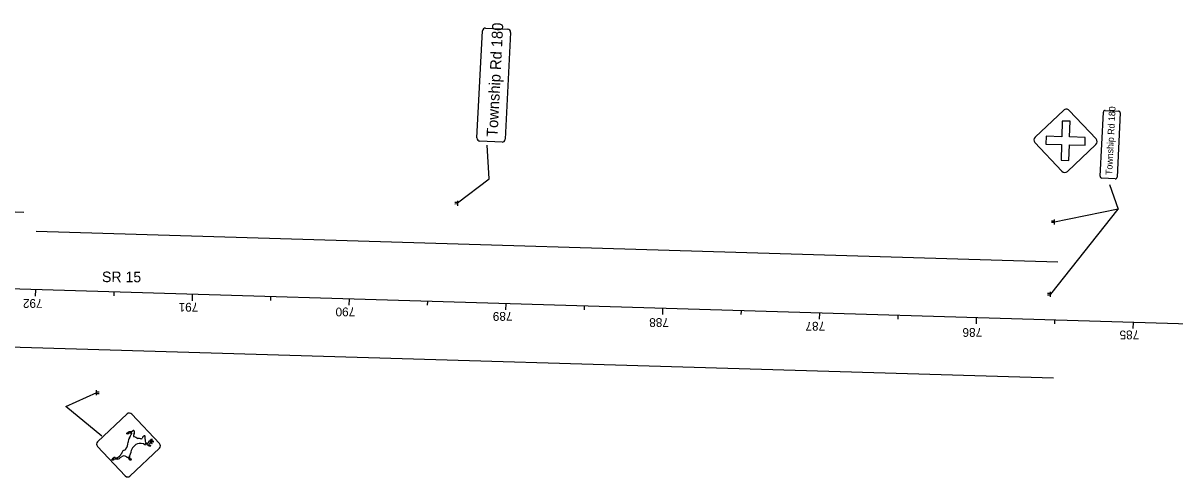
# Model space of a CAD drawing. Extents: x 1658454 to 1663955, y 480219 to 484109.
# Drawn here: x 1661744 to 1662479, y 482582 to 482871 of the extents above; entities that cross this region are included whole.
import ezdxf

# ---------------------------------------------------------------- set-up
doc = ezdxf.new("R2010")
doc.units = 0
for name, color, linetype in [('Default', 7, 'Continuous'), ('PM_P_Edge_Line', 7, 'Continuous'), ('PM_X_Lane_Line', 7, 'Continuous'), ('SC_Scratch1', 7, 'Continuous'), ('SN_X_Public', 7, 'Continuous'), ('SV_X_CL_Survey_50', 7, 'Continuous'), ('SV_X_Text', 7, 'Continuous')]:
    doc.layers.add(name, color=color, linetype=linetype)

msp = doc.modelspace()

# ---------------------------------------------------------------- linework, layer by layer
at = {"layer": 'Default'}
for p, q in [((1661752.21, 482700.93), (1661752.09, 482696.94)), ((1661802.19, 482699.45), (1661802.12, 482697.05)), ((1661852.17, 482697.97), (1661852.05, 482693.97)), ((1661902.15, 482696.48), (1661902.07, 482694.08)), ((1661952.12, 482695), (1661952.01, 482691)), ((1662002.1, 482693.51), (1662002.03, 482691.12)), ((1662052.08, 482692.03), (1662051.96, 482688.03)), ((1662102.06, 482690.55), (1662101.99, 482688.15)), ((1662152.04, 482689.06), (1662151.92, 482685.06)), ((1662202.01, 482687.58), (1662201.94, 482685.18)), ((1662251.99, 482686.1), (1662251.87, 482682.1)), ((1662301.97, 482684.61), (1662301.9, 482682.21)), ((1662351.95, 482683.13), (1662351.83, 482679.13)), ((1662401.93, 482681.64), (1662401.85, 482679.24)), ((1662451.9, 482680.16), (1662451.79, 482676.16))]:
    msp.add_line(p, q, dxfattribs=at)
at = {"layer": 'PM_P_Edge_Line'}
msp.add_line((1661744.74, 482750.18), (1661423, 482759.73), dxfattribs=at)
at = {"layer": 'PM_X_Lane_Line'}
for p, q in [((1662403.89, 482718.6), (1661752.68, 482737.94)), ((1662401.15, 482644.65), (1661431.82, 482673.43))]:
    msp.add_line(p, q, dxfattribs=at)
at = {"layer": 'SC_Scratch1'}
for p, q in [((1662039.2, 482867.58), (1662053.34, 482866.86)), ((1662033.69, 482797.69), (1662037.18, 482865.76)), ((1662055.16, 482864.84), (1662051.67, 482796.77)), ((1662434.21, 482815.16), (1662442.7, 482814.73)), ((1662406.74, 482808.39), (1662406.44, 482798.39)), ((1662411.74, 482808.24), (1662406.74, 482808.39)), ((1662411.44, 482798.25), (1662411.74, 482808.24)), ((1662430.91, 482773.23), (1662433, 482814.07)), ((1662443.79, 482813.52), (1662441.69, 482772.67)), ((1662049.65, 482794.95), (1662035.51, 482795.67)), ((1662396.45, 482798.69), (1662396.3, 482793.69)), ((1662396.3, 482793.69), (1662406.29, 482793.4)), ((1662406.44, 482798.39), (1662396.45, 482798.69)), ((1662406.29, 482793.4), (1662406, 482783.4)), ((1662411, 482783.25), (1662411.29, 482793.25)), ((1662411.29, 482793.25), (1662421.29, 482792.95)), ((1662421.44, 482797.95), (1662411.44, 482798.25)), ((1662421.29, 482792.95), (1662421.44, 482797.95)), ((1662406, 482783.4), (1662411, 482783.25)), ((1662440.48, 482771.58), (1662432, 482772.02)), ((1662399.52, 482698.16), (1662442.34, 482752.22)), ((1661821.36, 482602.84), (1661819.61, 482602.98)), ((1661819.62, 482605.88), (1661820.32, 482606.09))]:
    msp.add_line(p, q, dxfattribs=at)
for points in [[(1662407.68, 482815.31), (1662389.48, 482798.17)], [(1662428.36, 482797.01), (1662411.21, 482815.21)], [(1662021.28, 482756.24), (1662041.51, 482771.51), (1662040.18, 482793.13)], [(1662389.38, 482794.63), (1662406.52, 482776.44)], [(1662410.06, 482776.33), (1662428.25, 482793.48)], [(1662436.92, 482768.07), (1662442.34, 482752.22), (1662400.85, 482743.79)], [(1661794.62, 482607.57), (1661771.6, 482626.55), (1661791.28, 482635.41)], [(1661791.89, 482604.09), (1661810.66, 482621.78)], [(1661813.63, 482621.69), (1661831.33, 482602.91)], [(1661811.2, 482608.94), (1661810.38, 482609.14), (1661810.57, 482609.52), (1661811.94, 482610.61), (1661813.36, 482610.57), (1661814.46, 482611.21)], [(1661813.46, 482609.69), (1661812.98, 482609.63), (1661812.3, 482609.61)], [(1661815.12, 482607.34), (1661816.27, 482606.95), (1661817.53, 482606.07)], [(1661822.23, 482601.86), (1661822.1, 482602.06), (1661821.28, 482602.57), (1661821.36, 482602.84), (1661821.36, 482602.84)], [(1661809.49, 482582.34), (1661791.8, 482601.12)], [(1661831.24, 482599.95), (1661812.46, 482582.25)], [(1661804.65, 482593.03), (1661802.16, 482593.11), (1661801.83, 482592.43), (1661800.89, 482592.46), (1661801.86, 482593.62)]]:
    msp.add_lwpolyline(points, dxfattribs=at)
for centre, radius, start, end in [((1662039.1, 482865.66), 1.92, 87.06499, 177.06499), ((1662053.24, 482864.94), 1.92, 357.06499, 87.06499), ((1662409.39, 482813.49), 2.5, 43.29934, 133.29934), ((1662434.15, 482814.01), 1.15, 87.06499, 177.06499), ((1662442.64, 482813.58), 1.15, 357.06499, 87.06499), ((1662035.61, 482797.59), 1.92, 177.06499, 267.06499), ((1662049.75, 482796.86), 1.92, 267.06499, 357.06499), ((1662391.2, 482796.35), 2.5, 133.29934, 223.29934), ((1662426.54, 482795.3), 2.5, 313.29934, 43.29934), ((1662408.34, 482778.15), 2.5, 223.29934, 313.29934), ((1662432.06, 482773.17), 1.15, 177.06499, 267.06499), ((1662440.54, 482772.73), 1.15, 267.06499, 357.06499), ((1661812.1, 482620.25), 2.1, 43.29934, 133.29934), ((1661812.32, 482608.34), 1.28, 91.2294, 151.83119), ((1661813.55, 482609.65), 0.0933, 20.88729, 155.71139), ((1661813.25, 482609.53), 0.413, 335.71139, 20.88729), ((1661814.75, 482610.7), 0.593, 2.63463, 120.19731), ((1661811.58, 482610.55), 3.77, 340.37674, 2.63463), ((1661793.33, 482602.56), 2.1, 133.29934, 223.29934), ((1661802.43, 482604.17), 8.84, 328.01516, 357.51473), ((1661816.93, 482603.54), 5.68, 147.98842, 177.51473), ((1661792.03, 482619.11), 23.69, 327.98842, 335.71139), ((1661816.27, 482607.75), 1.5, 169.5087, 187.08998), ((1661815.04, 482607.6), 0.265, 187.08998, 286.39166), ((1661822.85, 482606.53), 8.2, 160.37674, 169.5087), ((1661819.14, 482597.1), 5.9, 85.48239, 130.64019), ((1661818.19, 482601.65), 4.47, 71.32687, 98.40328), ((1661822.18, 482606.1), 1.86, 123.54589, 180.45104), ((1661821.32, 482607.4), 0.304, 68.59738, 123.54589), ((1661823.43, 482606.08), 2.56, 133.2682, 141.14025), ((1661821.81, 482607.79), 0.208, 29.98489, 133.2682), ((1661825.01, 482606.96), 3.16, 162.61939, 208.96231), ((1661822.23, 482602.81), 0.0793, 70.11299, 252.53377), ((1661821.43, 482602.28), 0.902, 332.40863, 30.2681), ((1661828.3, 482604.88), 6.08, 174.86266, 191.04392), ((1661820.89, 482599.1), 4.02, 52.27544, 70.11299), ((1661823.35, 482604.45), 1.26, 215.889, 320.70968), ((1661826, 482605.7), 4.32, 232.27544, 253.45969), ((1661782.51, 482637.87), 54.02, 320.70968, 322.266), ((1661824.83, 482602.28), 0.38, 116.06447, 232.31736), ((1661825.84, 482601.53), 1.61, 64.85983, 137.12241), ((1661826.52, 482604.2), 1.42, 79.03378, 154.83056), ((1661825.51, 482603.63), 0.134, 124.26495, 320.99305), ((1661826.74, 482601.82), 2.32, 74.92516, 124.26495), ((1661826, 482604.63), 0.43, 99.0122, 198.23396), ((1661825.45, 482610.48), 5.99, 271.42436, 279.91), ((1661825.63, 482601.91), 1.63, 50.5294, 90.53258), ((1661825.74, 482606.3), 1.26, 279.0122, 326.20978), ((1661826.67, 482603.48), 1.12, 52.36495, 99.91), ((1661826.59, 482603.08), 0.117, 233.61235, 50.5294), ((1661827.24, 482604.22), 0.187, 304.23373, 52.36495), ((1661829.8, 482601.47), 2.1, 313.29934, 43.29934), ((1661803.65, 482596.84), 2.9, 257.26592, 319.33316), ((1661789.93, 482608.63), 20.99, 319.33316, 325.64071), ((1661808.54, 482592.73), 2.35, 45.24982, 128.22151), ((1661805.76, 482597.81), 1.82, 325.64071, 349.33227), ((1661809.02, 482597.2), 1.5, 100.6889, 169.33226), ((1661808.41, 482600.43), 1.79, 280.6889, 328.01516), ((1661807.79, 482597.93), 5.27, 324.41086, 349.41533), ((1661816.33, 482595.17), 4.26, 184.22664, 204.53147), ((1661830.44, 482593.69), 17.77, 164.35622, 169.41533), ((1661819.42, 482596.78), 6.32, 130.64019, 164.35622), ((1661825.23, 482602.81), 1.04, 232.31736, 285.67774), ((1661825.23, 482602.22), 0.803, 234.85898, 290.04994), ((1661825.57, 482601.63), 0.179, 250.92094, 105.67774), ((1661802.76, 482592.88), 1.17, 77.26592, 140.16796), ((1661804.1, 482595.64), 2.67, 281.92633, 307.00815), ((1661756.06, 482659.37), 82.48, 307.00815, 308.22151), ((1661810.77, 482594.98), 0.812, 225.24982, 326.89345), ((1661814.75, 482594.77), 3.31, 184.18543, 214.58719), ((1661812.78, 482593.41), 0.912, 214.58719, 325.97364), ((1661815.58, 482598.79), 6.23, 239.89954, 250.86955), ((1661811.02, 482583.78), 2.1, 223.29934, 313.29934)]:
    msp.add_arc(centre, radius, start, end, dxfattribs=at)
at = {"layer": 'SN_X_Public'}
for p, q in [((1662021.22, 482756.52), (1662019.62, 482756.5)), ((1662021.22, 482757.64), (1662021.24, 482754.44)), ((1662021.23, 482755.56), (1662019.63, 482755.54)), ((1662021.23, 482756.04), (1662021.23, 482756.04)), ((1662401.57, 482744.64), (1662399.97, 482744.62)), ((1662401.57, 482743.68), (1662399.97, 482743.66)), ((1662401.56, 482745.76), (1662401.58, 482742.56)), ((1662401.57, 482744.16), (1662401.57, 482744.16)), ((1662399.02, 482698.45), (1662397.42, 482698.44)), ((1662399.01, 482699.57), (1662399.04, 482696.38)), ((1662399.03, 482697.97), (1662399.03, 482697.97)), ((1662399.03, 482697.49), (1662397.43, 482697.48)), ((1661791.22, 482633.8), (1661791.24, 482637)), ((1661791.23, 482635.88), (1661792.83, 482635.87)), ((1661791.23, 482635.4), (1661791.23, 482635.4)), ((1661791.23, 482634.92), (1661792.83, 482634.91))]:
    msp.add_line(p, q, dxfattribs=at)
at = {"layer": 'SV_X_CL_Survey_50'}
msp.add_line((1663951.73, 482635.63), (1658453.66, 482798.87), dxfattribs=at)

# ---------------------------------------------------------------- texts
at = {"layer": 'SC_Scratch1'}
for s, height, rotation, p in [('Township Rd 180', 7.0009, 87.06499, (1662046.76, 482798.15)), ('Township Rd 180', 4.2005, 87.06499, (1662438.55, 482773.98)), ('SR 15', 6.72, 359.70542, (1661794.62, 482705.81))]:
    msp.add_text(s, height=height, rotation=rotation, dxfattribs=at).set_placement(p)
at = {"layer": 'SV_X_Text'}
for s, p in [('792', (1661756.73, 482695.04)), ('791', (1661856, 482692.64)), ('790', (1661956.01, 482689.67)), ('789', (1662056.25, 482686.81)), ('788', (1662155.98, 482682.9)), ('787', (1662255.56, 482680.54)), ('786', (1662355.66, 482676.59)), ('785', (1662455.76, 482675.02))]:
    msp.add_text(s, height=5.6, rotation=180.53411, dxfattribs=at).set_placement(p)

doc.saveas('drawing.dxf')
